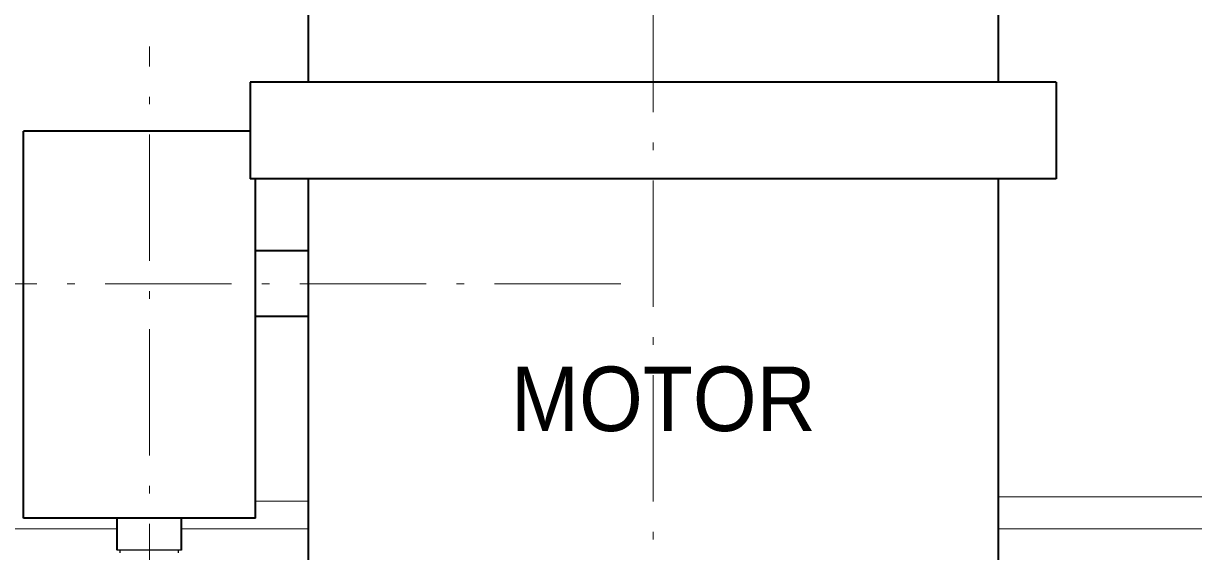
# Model space of a CAD drawing. Extents: x -4160 to -2690, y -474 to 714.
# Drawn here: x -3643.41 to -3617.49, y -316.36 to -304.66 of the extents above; entities that cross this region are included whole.
import ezdxf
from ezdxf.enums import TextEntityAlignment as Align

# ---------------------------------------------------------------- set-up
doc = ezdxf.new("R2010")
doc.units = 0
doc.header["$LTSCALE"] = 0.56
doc.linetypes.add('DOT_DASHED', pattern=[7.7, 5, -1.2, 0.3, -1.2])
for name, color, linetype, lineweight in [('1', 7, 'Continuous', 25), ('2', 7, 'Continuous', 25), ('20', 7, 'Continuous', 13), ('3', 7, 'Continuous', 13), ('5', 7, 'Continuous', 35)]:
    doc.layers.add(name, color=color, linetype=linetype, lineweight=lineweight)

msp = doc.modelspace()

# ---------------------------------------------------------------- linework, layer by layer
at = {"layer": '1'}
for p, q in [((-3639.9055, -316.3298), (-3641.3341, -316.3298)), ((-3641.2684, -316.3898), (-3641.2684, -316.3298)), ((-3639.9712, -316.3898), (-3639.9712, -316.3298))]:
    msp.add_line(p, q, dxfattribs=at)
at = {"layer": '20'}
for p, q in [((-3621.8185, -315.1441), (-3606.6213, -315.1441)), ((-3608.1713, -315.1441), (-3618.6456, -315.1441)), ((-3638.2684, -315.2441), (-3637.1042, -315.2441)), ((-3644.6513, -315.8583), (-3641.3342, -315.8583)), ((-3639.9056, -315.8583), (-3637.1042, -315.8583)), ((-3621.8185, -315.8583), (-3605.927, -315.8583)), ((-3614.2713, -315.8583), (-3618.6456, -315.8583))]:
    msp.add_line(p, q, dxfattribs=at)
at = {"layer": '3', "lineweight": 35}
for p, q in [((-3637.1041, -301.5298), (-3637.1041, -305.957)), ((-3621.8184, -301.5298), (-3621.8184, -305.957)), ((-3638.3898, -305.957), (-3638.3898, -308.1013)), ((-3620.5327, -305.957), (-3638.3898, -305.957)), ((-3620.5327, -305.957), (-3620.5327, -308.1013)), ((-3620.5327, -305.957), (-3620.5327, -308.1013)), ((-3638.3898, -307.0456), (-3643.4098, -307.0456)), ((-3643.4098, -315.6155), (-3643.4098, -307.0456)), ((-3620.5327, -308.1013), (-3638.3898, -308.1013)), ((-3638.2684, -315.6155), (-3638.2684, -308.1013)), ((-3637.1041, -308.1013), (-3637.1041, -322.387)), ((-3621.8184, -308.1013), (-3621.8184, -322.387)), ((-3637.1041, -309.6998), (-3638.2684, -309.6998)), ((-3637.1041, -311.1513), (-3638.2684, -311.1513)), ((-3638.2684, -315.6155), (-3643.4098, -315.6155)), ((-3641.3341, -316.3298), (-3641.3341, -315.6155)), ((-3639.9055, -316.3298), (-3639.9055, -315.6155))]:
    msp.add_line(p, q, dxfattribs=at)
at = {"layer": '5', "linetype": 'DOT_DASHED', "lineweight": 13}
for p, q in [((-3629.4612, -295.2013), (-3629.4612, -400.7869)), ((-3640.6198, -318.5455), (-3640.6198, -305.167)), ((-3630.1755, -310.4255), (-3644.3327, -310.4255))]:
    msp.add_line(p, q, dxfattribs=at)

# ---------------------------------------------------------------- texts
at = {"layer": '2', "width": 0.95}
msp.add_text('MOTOR', height=1.429, dxfattribs=at).set_placement((-3629.2348, -313.6898), align=Align.CENTER)

doc.saveas('drawing.dxf')
